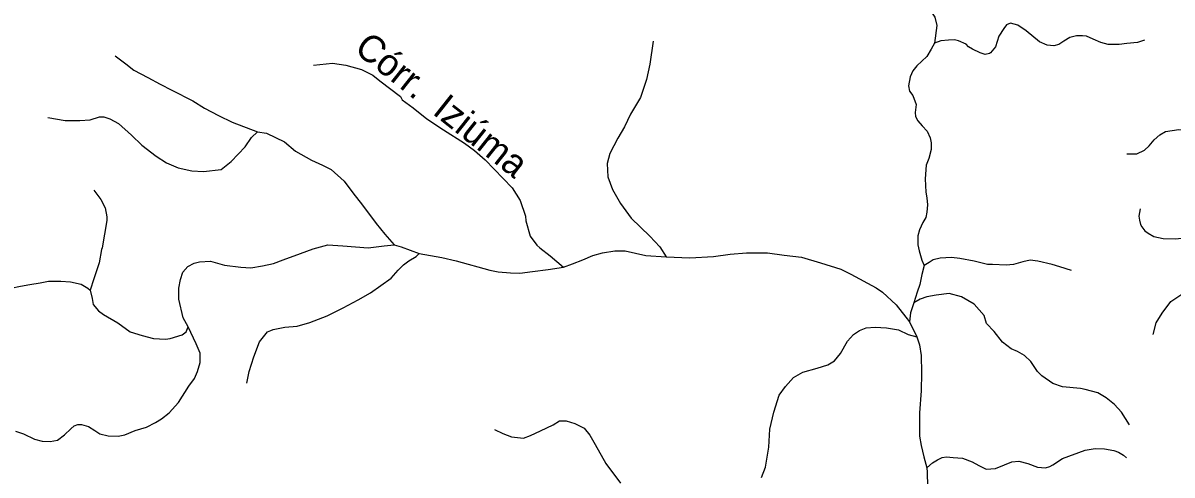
# Model space of a CAD drawing. Extents: x 436.3 to 500.4, y 8231 to 8286.4.
# Drawn here: x 456.78 to 465.31, y 8257.73 to 8261.09 of the extents above; entities that cross this region are included whole.
import ezdxf
from ezdxf.enums import TextEntityAlignment as Align

# ---------------------------------------------------------------- set-up
doc = ezdxf.new("R2010")
doc.units = 0
doc.header["$LTSCALE"] = 0.08
doc.linetypes.add('LONG_DASHED', pattern=[7.5, 6, -1.5])
doc.layers.add('61', color=7, linetype='Continuous')
doc.layers.add('9', color=7, linetype='LONG_DASHED', lineweight=25)

msp = doc.modelspace()

# ---------------------------------------------------------------- linework, layer by layer
at = {"layer": '9'}
for points in [[(463.5367, 8261.4765), (463.4988, 8261.4435), (463.4549, 8261.3898), (463.4355, 8261.3557), (463.4355, 8261.2924), (463.46, 8261.2487), (463.4649, 8261.2438), (463.5087, 8261.1902), (463.5331, 8261.1611), (463.5528, 8261.1319), (463.5674, 8261.0687), (463.5498, 8260.9386)], [(465.1097, 8260.9606), (465.0563, 8260.9442), (464.9781, 8260.9359), (464.9206, 8260.9278), (464.8383, 8260.9277), (464.7849, 8260.9442), (464.7272, 8260.9687), (464.6778, 8260.9895), (464.649, 8260.9936), (464.6038, 8260.9935), (464.5544, 8260.9811), (464.5091, 8260.9524), (464.4722, 8260.9277), (464.4352, 8260.9195), (464.3858, 8260.9236), (464.3282, 8260.9482), (464.2294, 8261.0302), (464.1676, 8261.0712), (464.1142, 8261.0876), (464.0853, 8261.0752), (464.0648, 8261.0465), (464.0279, 8260.989), (464.0032, 8260.911), (463.9663, 8260.8657), (463.958, 8260.8616), (463.9251, 8260.8534), (463.888, 8260.8656), (463.8305, 8260.8943), (463.8016, 8260.9107), (463.7844, 8260.931), (463.7267, 8260.9556), (463.6979, 8260.9638), (463.6527, 8260.9596), (463.596, 8260.9551), (463.5498, 8260.9386)], [(461.4604, 8260.9523), (461.4355, 8260.7835), (461.4108, 8260.6694), (461.366, 8260.5354), (461.2916, 8260.4112), (461.2469, 8260.317), (461.1972, 8260.2326), (461.1377, 8260.1184), (461.1178, 8260.044), (461.1227, 8259.945), (461.1575, 8259.8509), (461.2173, 8259.7471), (461.2968, 8259.6384), (461.436, 8259.5052), (461.5106, 8259.4263), (461.5576, 8259.3526)], [(463.5498, 8260.9386), (463.5252, 8260.8937), (463.4923, 8260.8403), (463.4183, 8260.7704), (463.3895, 8260.7334), (463.369, 8260.6882), (463.3566, 8260.6225), (463.365, 8260.5814), (463.3897, 8260.5486), (463.4144, 8260.483), (463.4053, 8260.4234), (463.4094, 8260.3947), (463.4259, 8260.3619), (463.4588, 8260.325), (463.4959, 8260.2841), (463.5165, 8260.2348), (463.5248, 8260.1979), (463.5248, 8260.1487), (463.5084, 8260.083), (463.4878, 8260.0338), (463.4798, 8259.9303), (463.484, 8259.8319), (463.4922, 8259.7909), (463.4965, 8259.7376), (463.4923, 8259.6843), (463.4842, 8259.6432), (463.4636, 8259.6063), (463.439, 8259.5529), (463.4266, 8259.5079), (463.4267, 8259.4423), (463.435, 8259.3971), (463.4556, 8259.3275), (463.4717, 8259.2884)], [(457.4646, 8260.845), (457.5457, 8260.7854), (457.6052, 8260.7367), (457.7078, 8260.6825), (457.7996, 8260.6338), (457.8861, 8260.5904), (458.0428, 8260.5091), (458.1292, 8260.4549), (458.2319, 8260.4008), (458.3345, 8260.352), (458.5219, 8260.2806)], [(458.938, 8260.7751), (459.079, 8260.789), (459.1778, 8260.7748), (459.2942, 8260.7429), (459.3788, 8260.7005), (459.4317, 8260.6582), (459.5834, 8260.5418), (459.5975, 8260.5171), (459.6787, 8260.4572), (459.7809, 8260.3761), (459.9043, 8260.2951), (460.0607, 8260.1948), (460.1347, 8260.142), (460.2123, 8260.0717), (460.4135, 8259.8645), (460.4735, 8259.7698), (460.5123, 8259.6539), (460.5158, 8259.6187), (460.5476, 8259.5064), (460.597, 8259.4397), (460.6182, 8259.4187), (460.6958, 8259.3592), (460.7944, 8259.2764)], [(456.9654, 8260.3871), (457.0952, 8260.3653), (457.2032, 8260.3651), (457.2789, 8260.3703), (457.3491, 8260.3918), (457.3815, 8260.3917), (457.4248, 8260.3754), (457.4895, 8260.3429), (457.5873, 8260.2557), (457.6629, 8260.18), (457.7711, 8260.0988), (457.8466, 8260.0501), (457.9331, 8260.0122), (458.0358, 8259.9904), (458.1222, 8259.9848), (458.2518, 8260.0007), (458.3275, 8260.0599), (458.4301, 8260.1676), (458.4788, 8260.2376), (458.5219, 8260.2806)], [(458.5219, 8260.2806), (458.5883, 8260.2704), (458.7234, 8260.2056), (458.8045, 8260.1354), (458.9234, 8260.0704), (459.0044, 8260.0325), (459.0693, 8259.9998), (459.1665, 8259.9137), (459.2313, 8259.8274), (459.3015, 8259.7357), (459.4042, 8259.6009), (459.469, 8259.5201), (459.5374, 8259.4417)], [(464.9778, 8260.1176), (465.0513, 8260.1176), (465.1093, 8260.145), (465.143, 8260.1755), (465.1797, 8260.2214), (465.2225, 8260.258), (465.2653, 8260.2824), (465.3632, 8260.2976), (465.4366, 8260.2915), (465.5314, 8260.2701), (465.6264, 8260.2273), (465.7487, 8260.1601), (465.8926, 8260.0807), (466.0486, 8260.0133), (466.2392, 8259.9541)], [(457.307, 8259.8483), (457.3601, 8259.7775), (457.3912, 8259.7155), (457.4045, 8259.6491), (457.4045, 8259.6226), (457.369, 8259.4192), (457.3646, 8259.406), (457.3468, 8259.3088), (457.307, 8259.1894), (457.2804, 8259.1055)], [(465.0759, 8259.7091), (465.0659, 8259.654), (465.0709, 8259.624), (465.0786, 8259.5915), (465.0886, 8259.574), (465.1112, 8259.5464), (465.1363, 8259.529), (465.179, 8259.504), (465.2467, 8259.4889), (465.3371, 8259.4864), (465.4349, 8259.4963), (465.5102, 8259.5138), (465.5653, 8259.5388), (465.6105, 8259.5588), (465.6732, 8259.5737), (465.7158, 8259.5862), (465.7504, 8259.5956)], [(465.1728, 8258.7764), (465.196, 8258.8624), (465.2392, 8258.9353), (465.3055, 8259.0213), (465.4151, 8259.0941), (465.518, 8259.157), (465.5578, 8259.2), (465.5877, 8259.2431), (465.6308, 8259.2961), (465.6707, 8259.3723), (465.7071, 8259.4816), (465.7369, 8259.5477), (465.7504, 8259.5956)], [(458.0079, 8258.8331), (457.9715, 8258.9004), (457.9386, 8259.0389), (457.9386, 8259.1192), (457.9496, 8259.1847), (457.9679, 8259.2394), (458.0044, 8259.2794), (458.052, 8259.3049), (458.0921, 8259.3157), (458.1726, 8259.3192), (458.2785, 8259.2899), (458.3991, 8259.2752), (458.4723, 8259.2713), (458.5599, 8259.2858), (458.6404, 8259.3039), (458.7134, 8259.3293), (458.8413, 8259.3764), (458.9364, 8259.4128), (459.044, 8259.4421), (459.1572, 8259.4347), (459.3437, 8259.42), (459.4642, 8259.4344), (459.5374, 8259.4417)], [(459.5374, 8259.4417), (459.5886, 8259.4271), (459.7238, 8259.3762)], [(460.7944, 8259.2764), (460.8616, 8259.3012), (460.9392, 8259.3296), (461.0134, 8259.3615), (461.0841, 8259.3828), (461.176, 8259.3971), (461.2537, 8259.3974), (461.4057, 8259.3626), (461.5576, 8259.3526)], [(458.4436, 8258.4154), (458.4607, 8258.5002), (458.4947, 8258.6103), (458.5373, 8258.7205), (458.5968, 8258.7968), (458.6223, 8258.8052), (458.6393, 8258.8137), (458.7245, 8258.8306), (458.818, 8258.8389), (458.9115, 8258.8643), (459.0392, 8258.915), (459.1583, 8258.9742), (459.2689, 8259.0335), (459.3625, 8259.0843), (459.5156, 8259.1945), (459.5666, 8259.2537), (459.6068, 8259.2937), (459.6471, 8259.3228), (459.7018, 8259.3556), (459.7238, 8259.3762)], [(459.7238, 8259.3762), (459.8919, 8259.3471), (459.998, 8259.3217), (460.2466, 8259.2528), (460.3103, 8259.2402), (460.4022, 8259.2333), (460.4694, 8259.2299), (460.5647, 8259.2442), (460.6813, 8259.2585), (460.7944, 8259.2764)], [(461.5576, 8259.3526), (461.7327, 8259.3461), (461.9094, 8259.3536), (462.033, 8259.3716), (462.1532, 8259.3826), (462.3087, 8259.3831), (462.4324, 8259.3658), (462.5618, 8259.3486), (462.7032, 8259.3068), (462.8551, 8259.2615), (462.9294, 8259.223), (463.1167, 8259.1214), (463.1626, 8259.0899), (463.2651, 8258.9951), (463.3361, 8258.9057), (463.3644, 8258.8706), (463.4182, 8258.7575)], [(464.5679, 8259.2504), (464.4814, 8259.279), (464.4238, 8259.2953), (464.3168, 8259.3199), (464.2592, 8259.328), (464.2057, 8259.3157), (464.1358, 8259.2951), (464.0823, 8259.291), (463.9794, 8259.2949), (463.9423, 8259.2949), (463.8436, 8259.3193), (463.7365, 8259.3397), (463.6748, 8259.3478), (463.5924, 8259.3435), (463.539, 8259.3311), (463.5102, 8259.3106), (463.4717, 8259.2884)], [(463.4717, 8259.2884), (463.4567, 8259.2203), (463.4403, 8259.1464), (463.4198, 8259.089), (463.3951, 8259.0112)], [(456.4429, 8259.0095), (456.4562, 8259.0493), (456.4917, 8259.0935), (456.5183, 8259.12), (456.5404, 8259.1332), (456.5714, 8259.1332), (456.6076, 8259.1215), (456.6394, 8259.1187), (456.6911, 8259.1205), (456.7626, 8259.1355), (456.8328, 8259.146), (456.9082, 8259.1591), (456.9713, 8259.1727), (457.0633, 8259.1722), (457.1342, 8259.1677), (457.2139, 8259.1499), (457.2627, 8259.1188), (457.2804, 8259.1055)], [(457.2804, 8259.1055), (457.2936, 8259.0436), (457.3025, 8258.9994), (457.3424, 8258.9507), (457.3779, 8258.9241), (457.4842, 8258.8621), (457.5772, 8258.7956), (457.6659, 8258.769), (457.75, 8258.7468), (457.8387, 8258.7423), (457.874, 8258.7466), (457.9627, 8258.773), (457.9937, 8258.795), (458.0079, 8258.8331)], [(464.9968, 8258.1049), (464.9392, 8258.1992), (464.8856, 8258.2566), (464.8238, 8258.3058), (464.7622, 8258.3427), (464.6675, 8258.3672), (464.6346, 8258.3754), (464.4988, 8258.3877), (464.4288, 8258.4123), (464.3465, 8258.4695), (464.3135, 8258.5023), (464.2641, 8258.576), (464.2188, 8258.6211), (464.1653, 8258.6497), (464.1199, 8258.6701), (464.054, 8258.7193), (463.9923, 8258.7971), (463.9346, 8258.8585), (463.9181, 8258.9158), (463.844, 8259.0017), (463.7493, 8259.0549), (463.6587, 8259.0793), (463.5631, 8259.0675), (463.4931, 8259.0551), (463.4437, 8259.0386), (463.3951, 8259.0112)], [(463.3951, 8259.0112), (463.3705, 8258.9373), (463.3644, 8258.8706)], [(456.7265, 8258.0582), (456.7838, 8258.0385), (456.8657, 8257.9989), (456.9242, 8257.9843), (456.9827, 8257.9806), (457.0375, 8257.9915), (457.0887, 8258.0315), (457.1362, 8258.0752), (457.1618, 8258.097), (457.1874, 8258.1079), (457.2166, 8258.1079), (457.2678, 8258.0933), (457.3153, 8258.0641), (457.3518, 8258.0385), (457.414, 8258.0239), (457.487, 8258.0201), (457.5382, 8258.031), (457.6149, 8258.0637), (457.699, 8258.0891), (457.7647, 8258.1218), (457.8086, 8258.1509), (457.8671, 8258.1946), (457.9366, 8258.2711), (458.0116, 8258.3922), (458.0554, 8258.4505), (458.0773, 8258.5014), (458.0956, 8258.567), (458.0957, 8258.6362), (458.0664, 8258.7055), (458.0079, 8258.8331)], [(462.2658, 8257.7141), (462.2952, 8257.7922), (462.3196, 8257.9386), (462.3265, 8258.0723), (462.3558, 8258.1991), (462.395, 8258.3259), (462.4439, 8258.3894), (462.5027, 8258.4578), (462.5713, 8258.497), (462.679, 8258.5266), (462.7573, 8258.5511), (462.8063, 8258.5806), (462.8503, 8258.6343), (462.9041, 8258.727), (462.9482, 8258.7759), (462.9922, 8258.8052), (463.0412, 8258.8248), (463.1097, 8258.8299), (463.193, 8258.8252), (463.2811, 8258.8108), (463.3545, 8258.7769), (463.4182, 8258.7575)], [(463.4182, 8258.7575), (463.4386, 8258.6984), (463.4494, 8258.6212), (463.453, 8258.4911), (463.4496, 8258.3574), (463.439, 8258.1956), (463.4386, 8258.0992), (463.4386, 8258.0219), (463.4493, 8257.9516), (463.4705, 8257.8672), (463.4938, 8257.7859)], [(460.2812, 8258.0698), (460.3449, 8258.0406), (460.4085, 8258.0165), (460.4967, 8258.0069), (460.5506, 8258.0265), (460.6241, 8258.0607), (460.7171, 8258.1048), (460.7661, 8258.1342), (460.8151, 8258.1343), (460.8787, 8258.115), (460.9473, 8258.0811), (460.9914, 8258.0276), (461.0306, 8257.9595), (461.109, 8257.8183), (461.2167, 8257.6723)], [(463.4938, 8257.7859), (463.5347, 8257.8222), (463.571, 8257.8448), (463.6073, 8257.8629), (463.639, 8257.8675), (463.6889, 8257.8631), (463.7571, 8257.8584), (463.8297, 8257.8314), (463.8797, 8257.8044), (463.9341, 8257.7774), (464.0021, 8257.782), (464.0702, 8257.8091), (464.1246, 8257.8318), (464.1746, 8257.8363), (464.2426, 8257.8183), (464.3152, 8257.7913), (464.3741, 8257.7867), (464.4059, 8257.7958), (464.4286, 8257.8094), (464.5011, 8257.8546), (464.6688, 8257.9178), (464.7414, 8257.9306), (464.8118, 8257.9278), (464.8815, 8257.9139)], [(464.8815, 8257.9139), (464.9156, 8257.9014), (464.9541, 8257.8792), (464.9743, 8257.8607)], [(463.4938, 8257.7859), (463.4953, 8257.7547), (463.4987, 8257.6473), (463.4917, 8257.4432), (463.4919, 8256.9858), (463.5025, 8256.8556), (463.5344, 8256.7219), (463.5697, 8256.6374), (463.6127, 8256.5613), (463.6516, 8256.4663), (463.6693, 8256.3641), (463.6763, 8256.283), (463.6727, 8256.1737), (463.6762, 8256.0714), (463.7081, 8255.9655), (463.7362, 8255.9162)]]:
    msp.add_lwpolyline(points, dxfattribs=at)

# ---------------------------------------------------------------- texts
at = {"layer": '61'}
msp.add_text('Córr.  Iziúma ', height=0.2, rotation=321.591, dxfattribs=at).set_placement((459.8601, 8260.3811), align=Align.CENTER)

doc.saveas('drawing.dxf')
